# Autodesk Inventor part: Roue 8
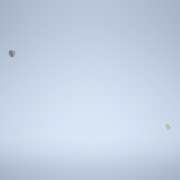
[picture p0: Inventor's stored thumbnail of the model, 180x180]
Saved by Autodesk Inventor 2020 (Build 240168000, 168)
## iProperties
Created: 2002-01
Part Number: Roue 8
Material: Laiton (jaune doux)
Document SubType Name: Modélisation
Designer: Philippe
Mass: 1.27972 g
Surface Area: 3.77147 cm^2
Volume: 0.151088 cm^3
Density: 8.47 g/cm^3
Appearance: Plastique (Blanc)
Shininess: 21.0
Angle Display Precision: 2
Document Length Units: 11269
Document Angle Units: 11279
Document Time Units: 11290
Document Mass Units: 11283
Document Length Units Precision: 3
Document Angle Units Precision: 2
Density: 0.0
Volumn: 0.0
Area: 0.0
PropertySet Name: Model Information
Control State: 0
Master: False
Checked Out: False
Author: Philippe
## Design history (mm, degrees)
sketch "Esquisse1"
  geometry: L1 (0, 0)-(5, 0); L2 (5, 0)-(5, 2); L3 (5, 2)-(2, 2); L4 (2, 2)-(2, 6.5); L5 (2, 6.5)-(0, 6.5); L6 (0, 6.5)-(0, 0)
  constraints: 12 end point, 4 parallel, 1 horizontal, 1 perpendicular, 1 other
  dimensions: "d0" = 2 distance of L1.end L2.end; "d1" = 6.5 distance between parallel lines of L5 L1; "d2" = 4 diameter of L4.end L6; "d3" = 10 diameter of L2 L6
revolve "Révolution1" sketch "Esquisse1" stored, may be unused: angle "d4" = 90 deg
sketch "Esquisse2"
  geometry: L1 (-0.548, 0.35)-(0.548, 0.35); C1 r 5 at (0, 0) reference; A1 r 0.65 centre (0, 0) between (-0.548, 0.35) and (0.548, 0.35)
  constraints: 2 end point, 2 point on circle, 1 centre point, 1 coincident, 1 horizontal
  dimensions: "d5" = 1.3 diameter of A1; "d59" = 1 dimension on A1 L1
extrude "Extrusion1" cut sketch "Esquisse2" extent not by distance; stored distance "d6" = 10; taper "d7" = 0 deg
node "Axe de construction1"
sketch "Esquisse6"
  geometry: C1 r 0.65 at (0, 0) reference; C2 r 1.5 at (0, 0); C3 r 3.9 at (0, 0)
  constraints: 2 centre point
  dimensions: "d32" = 3 diameter of C2; "d33" = 7.8 diameter of C3
extrude "Extrusion5" cut sketch "Esquisse6" distance "d34" = 0.2; taper "d35" = 0 deg
sketch "Esquisse7"
  geometry: C1 r 3.9 at (0, 0) reference; C2 r 2 at (0, 0) reference
extrude "Extrusion6" cut sketch "Esquisse7" distance "d36" = 0.8; taper "d37" = 0 deg
sketch "Esquisse8"
  geometry: L1 (0, 0)-(0, 5); C1 r 3.9 at (0, 0) reference; C2 r 4.7 at (0, 0); A1 r 5 centre (0, 0) between (-0.39, 4.985) and (0, 5) reference; A2 r 4.325 centre (0, 0) between (0.041, 4.325) and (-0.041, 4.325); A3 r 1.607 centre (-1.712, 4.071) between (-0.14, 4.404) and (-0.39, 4.985); A4 r 1.607 centre (1.712, 4.071) between (0.39, 4.985) and (0.14, 4.404); A5 r 0.1 centre (-0.042, 4.425) between (-0.14, 4.404) and (-0.041, 4.325); A6 r 0.1 centre (0.042, 4.425) between (0.041, 4.325) and (0.14, 4.404); A7 r 5 centre (0, 0) between (0.39, 4.985) and (-0.39, 4.985)
  constraints: 15 point on circle, 7 centre point, 4 tangent, 2 end point, 2 equal radius, 1 vertical
  dimensions: "d38" = 0.3 radial gap between concentric circles of C2 A1; "d39" = 0.375 radial gap between concentric circles of A2 C2; "d40" = 0.1 radius of A5
extrude "Extrusion7" cut sketch "Esquisse8" extent not by distance; stored distance "d41" = 10; taper "d42" = 0 deg
sketch "Esquisse9"
  geometry: L1 (-1.732, 1)-(-3.377, 1.95); L2 (0, 2)-(0, 3.9); L3 (-2.765, 2.751)-(-1, 1.732); L4 (2.765, 2.751)-(1, 1.732); L5 (1.732, 1)-(3.377, 1.95); A1 r 2 centre (0, 0) between (-1.732, 1) and (-1, 1.732) reference; A2 r 3.9 centre (0, 0) between (-2.765, 2.751) and (-3.377, 1.95) reference; A3 r 3.9 centre (0, 0) between (3.377, 1.95) and (2.765, 2.751); A4 r 2 centre (0, 0) between (1.732, 1) and (1, 1.732)
  constraints: 11 point on circle, 10 end point, 4 symmetric about line, 2 centre point, 2 point on line, 1 concentric, 2 other
  dimensions: "d46" = 1 distance between parallel lines of L3 L1; "d47" = 120 deg angle of L5 L1
extrude "Extrusion8" join sketch "Esquisse9" distance "d48" = 0.6; taper "d49" = 0 deg
sketch "Esquisse10"
  geometry: L1 (-0.238, 1.986)-(0, 1.786); L2 (0, 1.786)-(0.238, 1.986); L3 (0, 1.786)-(0, 2.143); C1 r 0.65 at (0, 0) reference; A1 r 2 centre (0, 0) between (1, 1.732) and (-1, 1.732) reference; A2 r 2 centre (0, 0) between (1, 1.732) and (-1, 1.732) reference
  constraints: 6 end point, 4 point on circle, 1 point on line, 1 vertical, 1 other
  dimensions: "d50" = 0.2 vertical distance of L1.start L1.end; "d51" = 100 deg angle of L2 L1
extrude "Extrusion9" cut sketch "Esquisse10" distance "d52" = 2.5; taper "d53" = 0 deg
node "Plan de construction1"
node "Plan de construction2"
node "Plan de construction3"
extrude "Extrusion10" join sketch "Esquisse2" stored distance "d60" = 2.5; taper "d61" = 0 deg
extrude "Extrusion11" join sketch "Esquisse2" stored distance "d62" = 2.5; taper "d63" = 0 deg
node "Solide1"
node "Corps solides"
node "Corps surfaciques"
pattern_circular "Réseau circulaire4" dims angle "d45" = 360 deg
pattern_circular "Réseau circulaire5" dims angle "d56" = 360 deg
other parameters: "d57" = -2.5, "d58" = -2.5, "d64" = 1.5
